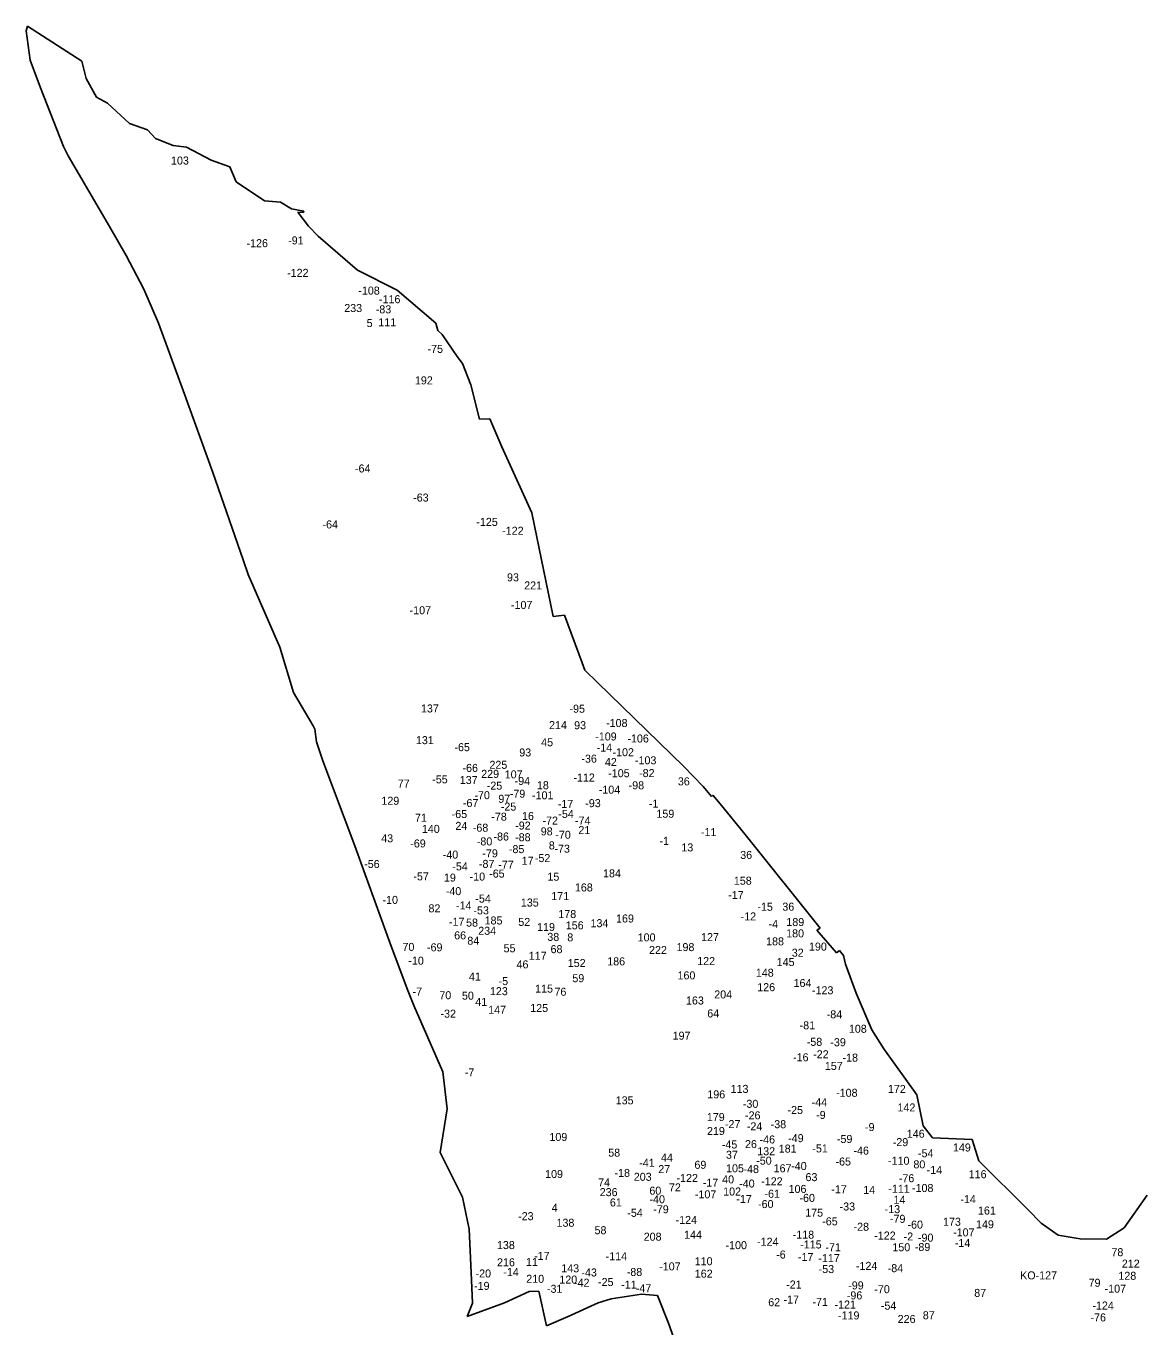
# Model space of a CAD drawing. Extents: x -783032 to -781233, y -975453 to -972360.
# Drawn here: x -782842 to -782039, y -973296 to -972360 of the extents above; entities that cross this region are included whole.
import ezdxf

# ---------------------------------------------------------------- set-up
doc = ezdxf.new("R2010")
doc.units = 0
doc.layers.add('Vrstva 13', color=7, linetype='Continuous')
doc.layers.add('Vrstva 24', color=7, linetype='Continuous')

msp = doc.modelspace()

# ---------------------------------------------------------------- linework, layer by layer
at = {"layer": 'Vrstva 13'}
for p, q in [((-782842.07, -972363.5), (-782840.93, -972360.01)), ((-782842.07, -972363.5), (-782839.14, -972384.69)), ((-782840.93, -972360.01), (-782801.87, -972385.24)), ((-782839.14, -972384.69), (-782831.58, -972404.58)), ((-782801.87, -972385.24), (-782798.8, -972397.72)), ((-782831.58, -972404.58), (-782815.01, -972446.59)), ((-782798.8, -972397.72), (-782791.33, -972411.29)), ((-782791.33, -972411.29), (-782783.41, -972415.57)), ((-782783.41, -972415.57), (-782767.66, -972430.23)), ((-782767.66, -972430.23), (-782754.74, -972434.6)), ((-782754.74, -972434.6), (-782748.94, -972440.83)), ((-782748.94, -972440.83), (-782736.28, -972445.93)), ((-782815.01, -972446.59), (-782811.66, -972453.32)), ((-782736.28, -972445.93), (-782726.59, -972447.14)), ((-782726.59, -972447.14), (-782708.82, -972456.48)), ((-782811.66, -972453.32), (-782782.06, -972504.26)), ((-782708.82, -972456.48), (-782695.57, -972461.21)), ((-782695.57, -972461.21), (-782690.9, -972472.15)), ((-782690.9, -972472.15), (-782670.61, -972485.91)), ((-782670.61, -972485.91), (-782659.09, -972486.75)), ((-782659.09, -972486.75), (-782651.03, -972491.53)), ((-782651.03, -972491.53), (-782642.18, -972493.23)), ((-782642.59, -972494.28), (-782646.55, -972494.05)), ((-782646.55, -972494.05), (-782638.77, -972504.03)), ((-782642.18, -972493.23), (-782642.59, -972494.28)), ((-782782.06, -972504.26), (-782770.15, -972525.05)), ((-782638.77, -972504.03), (-782632.03, -972511.31)), ((-782632.03, -972511.31), (-782603.52, -972535.58)), ((-782770.15, -972525.05), (-782757.42, -972549.41)), ((-782603.52, -972535.58), (-782575.21, -972550.14)), ((-782757.42, -972549.41), (-782746.7, -972573.88)), ((-782575.21, -972550.14), (-782547.27, -972573.91)), ((-782746.7, -972573.88), (-782729.15, -972622.14)), ((-782547.27, -972573.91), (-782545.9, -972579.19)), ((-782545.9, -972579.19), (-782542.63, -972581.93)), ((-782542.63, -972581.93), (-782531.88, -972597.68)), ((-782531.88, -972597.68), (-782528.17, -972602.79)), ((-782528.17, -972602.79), (-782522.07, -972618.13)), ((-782522.07, -972618.13), (-782515.84, -972642.78)), ((-782729.15, -972622.14), (-782707.62, -972681.32)), ((-782515.84, -972642.78), (-782508.47, -972642.59)), ((-782508.47, -972642.59), (-782499.71, -972662.72)), ((-782499.71, -972662.72), (-782478.14, -972710.17)), ((-782707.62, -972681.32), (-782685.79, -972744.19)), ((-782478.14, -972710.17), (-782462.82, -972784.77)), ((-782685.79, -972744.19), (-782682.37, -972754.55)), ((-782682.37, -972754.55), (-782678.23, -972763.97)), ((-782678.23, -972763.97), (-782659.4, -972806.95)), ((-782462.82, -972784.77), (-782454.74, -972783.9)), ((-782454.74, -972783.9), (-782442.08, -972818.15)), ((-782659.4, -972806.95), (-782649.62, -972839.48)), ((-782442.08, -972818.15), (-782440.03, -972823.43)), ((-782440.03, -972823.43), (-782369, -972892.88)), ((-782649.62, -972839.48), (-782635.59, -972863.43)), ((-782635.59, -972863.43), (-782634.41, -972866.03)), ((-782634.41, -972866.03), (-782633.06, -972875.09)), ((-782633.06, -972875.09), (-782628.66, -972888.81)), ((-782628.66, -972888.81), (-782605.57, -972949.88)), ((-782369, -972892.88), (-782354.87, -972907.08)), ((-782354.87, -972907.08), (-782349.09, -972914.28)), ((-782349.09, -972914.28), (-782347.91, -972913.46)), ((-782347.91, -972913.46), (-782342.77, -972919.56)), ((-782342.77, -972919.56), (-782324.85, -972941.78)), ((-782324.85, -972941.78), (-782270.79, -973009)), ((-782605.57, -972949.88), (-782598.12, -972970.59)), ((-782598.12, -972970.59), (-782580.32, -973019.48)), ((-782273.19, -973010.58), (-782270.79, -973009)), ((-782259.08, -973026.8), (-782273.19, -973010.58)), ((-782580.32, -973019.48), (-782567.89, -973052.72)), ((-782256.93, -973025.25), (-782259.08, -973026.8)), ((-782254.07, -973028.72), (-782256.93, -973025.25)), ((-782252.5, -973035.05), (-782254.07, -973028.72)), ((-782244.85, -973055.91), (-782252.5, -973035.05)), ((-782567.89, -973052.72), (-782563.09, -973064.86)), ((-782233.65, -973082.15), (-782244.85, -973055.91)), ((-782563.09, -973064.86), (-782542.33, -973112.57)), ((-782225.08, -973095.91), (-782233.65, -973082.15)), ((-782201.22, -973129.08), (-782225.08, -973095.91)), ((-782542.33, -973112.57), (-782539.23, -973139.18)), ((-782201.22, -973129.08), (-782196.68, -973151.41)), ((-782539.23, -973139.18), (-782544.09, -973170.46)), ((-782196.68, -973151.41), (-782190.03, -973159.88)), ((-782190.03, -973159.88), (-782161.52, -973161.16)), ((-782161.52, -973161.16), (-782156.78, -973176.56)), ((-782544.09, -973170.46), (-782528.05, -973202.56)), ((-782156.78, -973176.56), (-782121.53, -973211.46)), ((-782528.05, -973202.56), (-782523.29, -973225.64)), ((-782052.14, -973224.77), (-782035.47, -973201.26)), ((-782121.53, -973211.46), (-782111.79, -973221.48)), ((-782523.29, -973225.64), (-782521.94, -973256.92)), ((-782111.79, -973221.48), (-782099.68, -973230.05)), ((-782064.8, -973232.79), (-782052.14, -973224.77)), ((-782099.68, -973230.05), (-782083.83, -973232.6)), ((-782083.83, -973232.6), (-782064.8, -973232.79)), ((-782521.94, -973256.92), (-782520.91, -973278.94)), ((-782480.14, -973270.47), (-782497.77, -973278.77)), ((-782473.1, -973270.29), (-782480.14, -973270.47)), ((-782467.72, -973295.35), (-782473.1, -973270.29)), ((-782399.4, -973272.52), (-782421.04, -973275.76)), ((-782387.72, -973273.35), (-782399.4, -973272.52)), ((-782387.72, -973273.35), (-782379.89, -973293.35)), ((-782497.77, -973278.77), (-782524.69, -973288.57)), ((-782520.91, -973278.94), (-782524.69, -973288.57)), ((-782430.47, -973278.72), (-782452.05, -973288.43)), ((-782421.04, -973275.76), (-782430.47, -973278.72)), ((-782452.05, -973288.43), (-782467.72, -973295.35)), ((-782379.89, -973293.35), (-782373.16, -973312.3))]:
    msp.add_line(p, q, dxfattribs=at)

# ---------------------------------------------------------------- texts
at = {"layer": 'Vrstva 24'}
for s, p in [('103', (-782737.772, -972459.672)), ('-126', (-782683.466, -972519.14)), ('-91', (-782653.516, -972517.15)), ('-122', (-782654.262, -972540.48)), ('-108', (-782603.019, -972553.25)), ('-116', (-782588.178, -972559.45)), ('233', (-782613.163, -972565.802)), ('-83', (-782590.49, -972566.74)), ('5', (-782597.023, -972576.582)), ('111', (-782588.631, -972576.062)), ('-75', (-782553.242, -972595.18)), ('192', (-782562.339, -972617.862)), ('-64', (-782605.448, -972681.22)), ('-63', (-782563.593, -972702.18)), ('-125', (-782518.152, -972719.67)), ('-64', (-782628.798, -972721.5)), ('-122', (-782499.562, -972726.05)), ('93', (-782496.086, -972759.552)), ('221', (-782483.725, -972765.382)), ('-107', (-782566.141, -972783.25)), ('-107', (-782493.241, -972779.42)), ('137', (-782557.967, -972853.912)), ('-95', (-782451.133, -972854.11)), ('214', (-782465.841, -972865.892)), ('93', (-782447.796, -972865.962)), ('-108', (-782424.809, -972864.4)), ('131', (-782561.628, -972876.712)), ('45', (-782471.508, -972878.212)), ('-109', (-782432.602, -972874.06)), ('-106', (-782409.462, -972875.52)), ('-65', (-782533.893, -972881.76)), ('93', (-782487.256, -972885.572)), ('-14', (-782431.568, -972882.01)), ('-102', (-782420.179, -972885.38)), ('-66', (-782528.106, -972896.7)), ('225', (-782508.723, -972894.462)), ('-36', (-782442.583, -972890.03)), ('42', (-782425.658, -972892.442)), ('-103', (-782404.049, -972891.21)), ('-55', (-782549.88, -972904.91)), ('137', (-782530.067, -972905.372)), ('229', (-782514.636, -972900.962)), ('107', (-782497.724, -972901.342)), ('-94', (-782490.588, -972906.1)), ('-112', (-782448.314, -972903.6)), ('-105', (-782423.279, -972900.5)), ('-82', (-782401.07, -972900.42)), ('36', (-782373.196, -972906.372)), ('77', (-782574.667, -972907.922)), ('-70', (-782519.518, -972916.31)), ('-25', (-782510.66, -972909.47)), ('-79', (-782494.085, -972915.22)), ('-101', (-782478.102, -972916.4)), ('18', (-782474.575, -972909.142)), ('-104', (-782430.074, -972912.35)), ('-98', (-782408.583, -972909.21)), ('129', (-782586.449, -972920.322)), ('-67', (-782527.805, -972921.95)), ('97', (-782502.338, -972918.912)), ('-25', (-782500.54, -972924.52)), ('-17', (-782459.584, -972922.61)), ('-93', (-782439.803, -972922.05)), ('-1', (-782394.042, -972922.36)), ('71', (-782562.277, -972932.552)), ('-65', (-782535.893, -972929.89)), ('-78', (-782507.392, -972931.76)), ('16', (-782485.279, -972931.292)), ('-72', (-782470.582, -972934.59)), ('-54', (-782459.165, -972929.82)), ('-74', (-782447.158, -972934.55)), ('159', (-782388.599, -972929.672)), ('140', (-782557.327, -972940.582)), ('24', (-782533.188, -972938.382)), ('-68', (-782520.683, -972939.72)), ('-92', (-782490.193, -972938.17)), ('98', (-782471.806, -972942.352)), ('21', (-782444.765, -972941.422)), ('-11', (-782356.594, -972942.87)), ('43', (-782586.558, -972947.332)), ('-69', (-782565.666, -972951.03)), ('-80', (-782517.816, -972949.58)), ('-86', (-782505.813, -972946.06)), ('-88', (-782490.24, -972946.56)), ('8', (-782466.013, -972952.442)), ('-70', (-782461.348, -972944.8)), ('-1', (-782386.392, -972949.16)), ('13', (-782370.675, -972953.902)), ('-40', (-782542.312, -972959.1)), ('-79', (-782513.815, -972958.15)), ('-85', (-782494.71, -972955.13)), ('-52', (-782476.05, -972961.57)), ('-73', (-782461.962, -972954.82)), ('36', (-782328.316, -972959.302)), ('-56', (-782598.813, -972965.84)), ('-54', (-782535.435, -972967.55)), ('-87', (-782516.272, -972965.75)), ('-77', (-782502.364, -972966.29)), ('17', (-782485.527, -972963.472)), ('184', (-782427.001, -972972.552)), ('-57', (-782563.412, -972974.73)), ('19', (-782541.459, -972975.602)), ('-10', (-782522.979, -972974.88)), ('-65', (-782508.923, -972972.73)), ('15', (-782467.005, -972974.962)), ('158', (-782332.905, -972977.852)), ('-40', (-782540.122, -972985.35)), ('-54', (-782518.855, -972990.7)), ('171', (-782464.23, -972988.892)), ('168', (-782447.249, -972982.692)), ('-17', (-782336.964, -972988.13)), ('-10', (-782585.649, -972991.64)), ('82', (-782552.573, -972997.742)), ('-14', (-782532.788, -972995.66)), ('-53', (-782520.25, -972999.2)), ('135', (-782486.125, -972993.542)), ('-15', (-782315.992, -972996.61)), ('36', (-782298.036, -972996.532)), ('-17', (-782537.864, -973007.42)), ('58', (-782525.523, -973007.982)), ('185', (-782512.205, -973006.462)), ('52', (-782487.953, -973007.502)), ('178', (-782459.157, -973001.832)), ('156', (-782453.799, -973009.952)), ('134', (-782436.021, -973008.422)), ('169', (-782417.643, -973005.042)), ('-12', (-782328.022, -973003.54)), ('-4', (-782307.935, -973009.01)), ('189', (-782295.149, -973007.582)), ('66', (-782534.089, -973017.192)), ('234', (-782516.788, -973013.882)), ('119', (-782474.441, -973011.152)), ('38', (-782467.073, -973018.262)), ('8', (-782452.713, -973018.632)), ('100', (-782402.089, -973018.642)), ('127', (-782356.467, -973018.422)), ('180', (-782295.272, -973015.752)), ('70', (-782571.281, -973025.492)), ('-69', (-782553.636, -973025.78)), ('84', (-782524.618, -973021.012)), ('55', (-782498.533, -973026.472)), ('68', (-782464.756, -973027.112)), ('222', (-782393.913, -973027.672)), ('198', (-782374.139, -973025.622)), ('188', (-782309.695, -973021.492)), ('190', (-782278.855, -973025.252)), ('-10', (-782567.069, -973035.39)), ('46', (-782489.232, -973038.052)), ('117', (-782480.43, -973031.862)), ('152', (-782452.385, -973037.062)), ('186', (-782423.989, -973035.892)), ('122', (-782359.265, -973035.662)), ('145', (-782302.121, -973036.382)), ('32', (-782291.243, -973029.662)), ('41', (-782523.481, -973046.812)), ('160', (-782373.425, -973045.972)), ('148', (-782317.081, -973044.052)), ('-5', (-782502.14, -973050.08)), ('115', (-782475.848, -973055.492)), ('59', (-782449.076, -973048.002)), ('126', (-782316.079, -973054.452)), ('164', (-782289.945, -973051.442)), ('-123', (-782276.712, -973056.67)), ('-7', (-782563.992, -973057.6)), ('70', (-782544.751, -973060.252)), ('50', (-782528.489, -973060.542)), ('41', (-782518.931, -973065.052)), ('123', (-782508.375, -973057.322)), ('76', (-782461.948, -973057.752)), ('163', (-782367.339, -973064.042)), ('204', (-782347.025, -973059.662)), ('-32', (-782543.93, -973073.52)), ('147', (-782509.623, -973070.732)), ('125', (-782479.375, -973069.452)), ('64', (-782352.022, -973073.352)), ('-84', (-782266.105, -973074)), ('-81', (-782285.592, -973081.93)), ('108', (-782250.162, -973084.382)), ('197', (-782376.941, -973089.342)), ('-58', (-782280.46, -973093.78)), ('-39', (-782263.493, -973094.06)), ('-22', (-782275.86, -973102.72)), ('-16', (-782290.326, -973104.9)), ('157', (-782267.447, -973111.122)), ('-18', (-782254.742, -973105.17)), ('-7', (-782526.462, -973115.74)), ('196', (-782351.993, -973131.572)), ('113', (-782335.238, -973127.642)), ('-108', (-782259.339, -973130.43)), ('172', (-782222.087, -973127.682)), ('135', (-782417.905, -973135.872)), ('-30', (-782326.446, -973138.37)), ('-44', (-782276.931, -973137.26)), ('142', (-782215.181, -973141.012)), ('179', (-782352.331, -973147.902)), ('-26', (-782324.873, -973146.67)), ('-25', (-782294.3, -973142.85)), ('-9', (-782273.733, -973146.37)), ('219', (-782352.239, -973157.952)), ('-27', (-782339.332, -973152.96)), ('-24', (-782323.595, -973154.6)), ('-38', (-782306.41, -973153.05)), ('-9', (-782238.573, -973155.11)), ('146', (-782208.495, -973159.902)), ('109', (-782465.575, -973162.242)), ('-45', (-782341.545, -973167.63)), ('26', (-782324.886, -973167.332)), ('-46', (-782314.398, -973164.03)), ('-49', (-782293.838, -973163.08)), ('-59', (-782258.763, -973163.68)), ('-29', (-782218.593, -973165.95)), ('58', (-782423.263, -973173.512)), ('44', (-782385.334, -973177.082)), ('37', (-782338.565, -973175.032)), ('132', (-782316.075, -973172.502)), ('181', (-782300.618, -973170.592)), ('-51', (-782276.452, -973170.47)), ('-46', (-782246.878, -973172.06)), ('-54', (-782200.465, -973173.98)), ('149', (-782175.305, -973169.782)), ('-41', (-782400.968, -973180.83)), ('27', (-782387.275, -973185.372)), ('69', (-782361.249, -973182.242)), ('105', (-782338.502, -973184.782)), ('-48', (-782325.965, -973185.36)), ('-50', (-782316.826, -973179.28)), ('167', (-782304.291, -973184.752)), ('-40', (-782291.652, -973183.14)), ('-65', (-782259.773, -973179.9)), ('-110', (-782222.012, -973179.36)), ('80', (-782203.739, -973181.942)), ('-14', (-782194.188, -973186)), ('109', (-782468.675, -973188.882)), ('74', (-782430.531, -973194.932)), ('-18', (-782418.752, -973188.09)), ('203', (-782404.899, -973190.882)), ('-122', (-782374.162, -973191.74)), ('-17', (-782355.264, -973195.11)), ('40', (-782341.325, -973192.762)), ('-40', (-782329.082, -973195.75)), ('-122', (-782313.242, -973194.16)), ('63', (-782281.366, -973191.132)), ('-76', (-782214.245, -973191.92)), ('116', (-782163.971, -973189.032)), ('236', (-782429.406, -973201.932)), ('60', (-782393.663, -973200.882)), ('72', (-782379.595, -973198.482)), ('-107', (-782360.941, -973203.5)), ('102', (-782340.602, -973201.472)), ('-61', (-782310.866, -973203.1)), ('106', (-782293.525, -973199.622)), ('-60', (-782285.71, -973206.05)), ('-17', (-782262.794, -973199.85)), ('14', (-782239.851, -973200.342)), ('-111', (-782221.788, -973199.5)), ('-108', (-782204.769, -973198.94)), ('4', (-782463.928, -973213.152)), ('61', (-782422.069, -973209.362)), ('-40', (-782393.582, -973207.05)), ('-79', (-782390.895, -973214.25)), ('-17', (-782331.114, -973206.87)), ('-60', (-782315.51, -973210.52)), ('-33', (-782256.83, -973212.25)), ('-13', (-782224.412, -973214.15)), ('14', (-782218.061, -973207.372)), ('-14', (-782169.968, -973206.97)), ('161', (-782157.301, -973215.172)), ('-23', (-782488.09, -973219.22)), ('138', (-782460.465, -973223.952)), ('-54', (-782409.555, -973216.8)), ('-124', (-782374.808, -973221.93)), ('175', (-782281.577, -973216.692)), ('-65', (-782269.333, -973222.93)), ('-79', (-782220.615, -973221.1)), ('-60', (-782207.99, -973225.3)), ('173', (-782182.437, -973223.242)), ('149', (-782158.705, -973225.082)), ('58', (-782433.113, -973229.332)), ('208', (-782397.759, -973233.992)), ('144', (-782368.707, -973232.572)), ('-118', (-782290.554, -973232.55)), ('-28', (-782246.8, -973226.83)), ('-122', (-782231.942, -973233.14)), ('-2', (-782210.76, -973233.84)), ('-90', (-782200.49, -973234.68)), ('-107', (-782175.171, -973230.86)), ('138', (-782503.335, -973240.012)), ('-100', (-782338.896, -973240.08)), ('-124', (-782316.208, -973237.61)), ('-115', (-782285.164, -973239.57)), ('-71', (-782267.054, -973241.58)), ('150', (-782218.872, -973241.582)), ('-89', (-782202.733, -973241.43)), ('-14', (-782173.978, -973238.51)), ('216', (-782503.249, -973252.382)), ('11', (-782482.408, -973252.172)), ('-17', (-782476.584, -973247.76)), ('-114', (-782425.13, -973248.06)), ('110', (-782361.055, -973251.652)), ('-6', (-782302.493, -973246.83)), ('-17', (-782286.824, -973248.61)), ('-117', (-782272.137, -973249.43)), ('78', (-782061.305, -973245.122)), ('212', (-782053.805, -973253.352)), ('-20', (-782518.696, -973260.43)), ('-14', (-782498.748, -973259.43)), ('143', (-782457.051, -973256.722)), ('-43', (-782442.575, -973259.72)), ('-88', (-782409.94, -973259.36)), ('-107', (-782386.601, -973255.35)), ('162', (-782361.009, -973260.592)), ('-53', (-782271.91, -973257.27)), ('-124', (-782245.108, -973254.99)), ('-84', (-782222.235, -973256.63)), ('KO-127', (-782126.957, -973261.822)), ('128', (-782056.295, -973262.112)), ('-19', (-782519.796, -973269.37)), ('210', (-782482.242, -973264.292)), ('-31', (-782467.362, -973271.46)), ('120', (-782458.432, -973264.842)), ('-42', (-782447.875, -973267.1)), ('-25', (-782430.62, -973266.6)), ('-11', (-782413.914, -973268.44)), ('-47', (-782403.448, -973271.07)), ('-21', (-782295.272, -973268.39)), ('-99', (-782250.626, -973269.03)), ('-70', (-782231.858, -973271.76)), ('79', (-782077.698, -973267.122)), ('-107', (-782066.191, -973271.39)), ('62', (-782308.166, -973281.142)), ('-17', (-782297.174, -973279.18)), ('-71', (-782276.344, -973280.87)), ('-96', (-782251.626, -973276.23)), ('87', (-782159.995, -973274.432)), ('-121', (-782260.484, -973282.79)), ('-119', (-782257.978, -973290.64)), ('-54', (-782227.165, -973283.61)), ('87', (-782196.985, -973290.512)), ('-124', (-782074.978, -973283.51)), ('226', (-782215.066, -973293.192)), ('-76', (-782076.375, -973292.08))]:
    msp.add_text(s, height=5.76, dxfattribs=at).set_placement(p)

doc.saveas('drawing.dxf')
